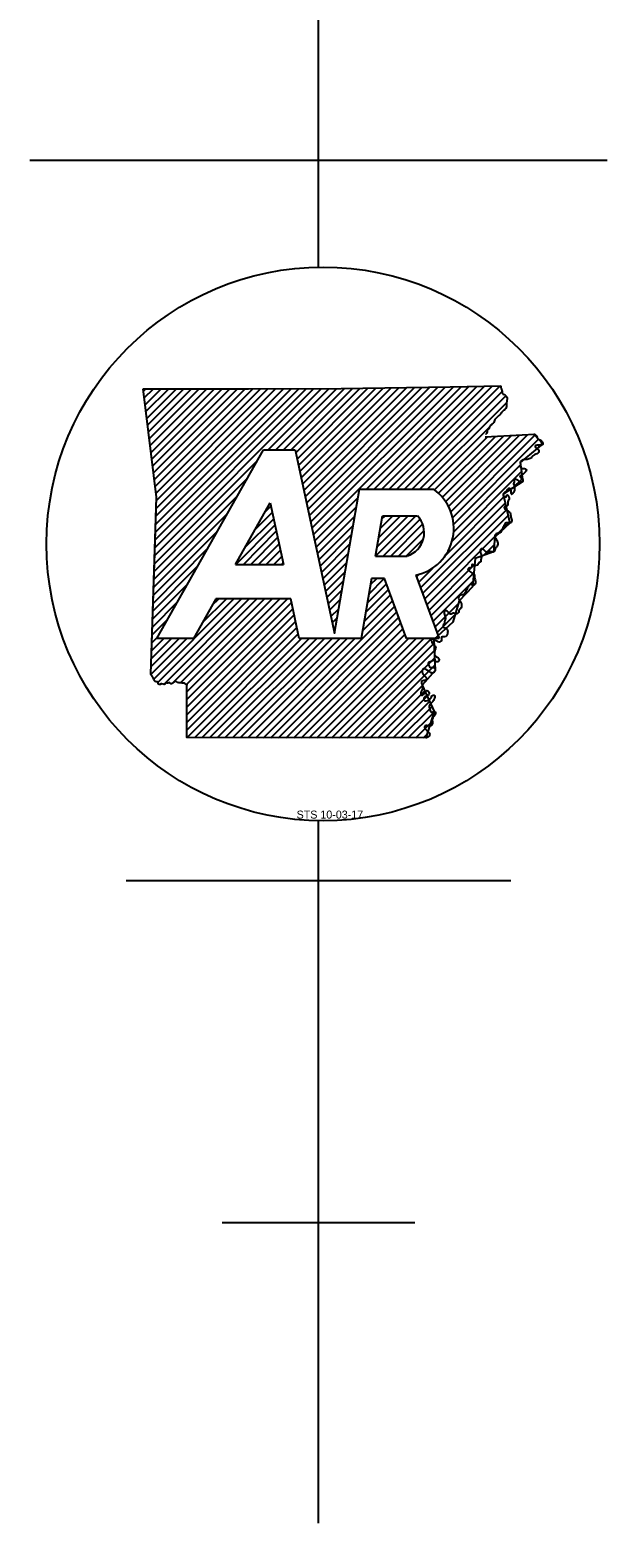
# Model space of a CAD drawing. Extents: x -43543 to 34500, y -13675 to 11152.
# Drawn here: x 5423 to 5949, y -831 to 528 of the extents above; entities that cross this region are included whole.
import ezdxf

# ---------------------------------------------------------------- set-up
doc = ezdxf.new("R2010")
doc.units = 0
doc.layers.add('R_Annotation', color=7, linetype='Continuous')

msp = doc.modelspace()

# ---------------------------------------------------------------- linework, layer by layer
at = {"layer": 'R_Annotation'}
for p, q in [((5685.7, 312.3), (5685.7, 1888.2)), ((5422.5, 409.7), (5948.8, 409.7)), ((5743.3, 110.2), (5837.1, 204)), ((5750.2, 110.2), (5844.2, 204.2)), ((5757.2, 110.2), (5851.4, 204.3)), ((5526, 199.4), (5528.2, 201.6)), ((5526.8, 193.2), (5535.2, 201.6)), ((5527.6, 187), (5542.1, 201.6)), ((5528.4, 180.8), (5549.1, 201.6)), ((5529.1, 174.6), (5556.1, 201.6)), ((5529.9, 168.5), (5563, 201.6)), ((5530.7, 162.3), (5570, 201.6)), ((5531.4, 156.1), (5576.9, 201.6)), ((5532.2, 149.9), (5583.9, 201.6)), ((5533, 143.7), (5590.9, 201.6)), ((5533.8, 137.5), (5597.8, 201.6)), ((5534.5, 131.3), (5604.8, 201.5)), ((5535.3, 125.1), (5611.8, 201.5)), ((5536.1, 118.9), (5618.7, 201.5)), ((5536.3, 49.5), (5688.5, 201.7)), ((5536.5, 56.7), (5681.5, 201.7)), ((5536.8, 63.9), (5674.5, 201.6)), ((5536.8, 112.7), (5625.7, 201.5)), ((5537, 71.1), (5667.6, 201.6)), ((5537.3, 78.3), (5660.6, 201.6)), ((5537.5, 85.5), (5653.6, 201.6)), ((5537.6, 106.5), (5632.7, 201.6)), ((5537.7, 92.7), (5646.6, 201.6)), ((5538, 99.9), (5639.6, 201.6)), ((5639.7, 145.9), (5695.5, 201.7)), ((5646.7, 145.9), (5702.5, 201.7)), ((5653.7, 145.9), (5709.5, 201.8)), ((5660.6, 145.9), (5716.6, 201.9)), ((5665, 143.3), (5723.6, 202)), ((5666.2, 137.6), (5730.7, 202.1)), ((5667.4, 131.8), (5737.8, 202.2)), ((5668.7, 126.1), (5744.9, 202.3)), ((5669.9, 120.4), (5752, 202.4)), ((5671.1, 114.6), (5759, 202.5)), ((5672.4, 108.9), (5766.1, 202.6)), ((5673.6, 103.2), (5773.2, 202.8)), ((5674.8, 97.4), (5780.3, 202.9)), ((5676, 91.7), (5787.3, 203)), ((5677.3, 85.9), (5794.4, 203.1)), ((5678.5, 80.2), (5801.5, 203.2)), ((5679.7, 74.5), (5808.6, 203.3)), ((5680.9, 68.7), (5815.7, 203.5)), ((5729.3, 110.2), (5822.8, 203.7)), ((5736.3, 110.2), (5830, 203.8)), ((5764.2, 110.2), (5852.9, 198.9)), ((5771.1, 110.2), (5856.3, 195.3)), ((5778.1, 110.2), (5857.2, 189.2)), ((5785.1, 110.2), (5841.3, 166.4)), ((5791.4, 109.5), (5839.9, 158)), ((5795.2, 106.4), (5847.3, 158.4)), ((5798.6, 102.8), (5854.6, 158.8)), ((5801.6, 98.8), (5861.9, 159.2)), ((5804.2, 94.5), (5869.3, 159.5)), ((5806.3, 89.6), (5876.6, 159.9)), ((5807.9, 84.2), (5883.2, 159.6)), ((5808.9, 78.2), (5886.5, 155.9)), ((5883.4, 145.8), (5889.7, 152.1)), ((5536.1, 42.3), (5630.1, 136.3)), ((5538.4, -25.7), (5635.5, 145.9)), ((5635.5, 145.9), (5664.4, 145.9)), ((5807.4, 62.9), (5870.7, 126.1)), ((5808.9, 71.3), (5869.9, 132.3)), ((5535.8, 35.1), (5621, 120.2)), ((5723, 110.2), (5790.5, 110.2)), ((5862.9, 111.3), (5871.5, 119.9)), ((5535.6, 27.9), (5611.9, 104.1)), ((5609.9, 41.7), (5641.6, 97.8)), ((5682.2, 63), (5721.7, 102.5)), ((5778.7, 20.2), (5855.9, 97.4)), ((5801.4, 49.9), (5854.6, 103.1)), ((5535.3, 20.7), (5602.8, 88.1)), ((5618.5, 57), (5644.8, 83.2)), ((5627.6, 73), (5643.5, 89)), ((5636.7, 89.1), (5642.3, 94.7)), ((5683.4, 57.3), (5720.2, 94.1)), ((5684.6, 51.5), (5718.8, 85.6)), ((5737.7, 49.3), (5774.4, 85.9)), ((5739.1, 57.7), (5767.4, 85.9)), ((5740.6, 66.1), (5760.4, 85.9)), ((5742.1, 74.5), (5753.5, 85.9)), ((5743.5, 83), (5746.5, 85.9)), ((5744.1, 85.9), (5775.7, 85.9)), ((5744.7, 49.3), (5778.2, 82.8)), ((5780.6, 15.1), (5857.2, 91.8)), ((5782.4, 10), (5858.5, 86.1)), ((5535.1, 13.5), (5593.7, 72)), ((5610.2, 41.7), (5646, 77.5)), ((5617.2, 41.7), (5647.2, 71.8)), ((5685.9, 45.8), (5717.3, 77.2)), ((5687.1, 40), (5715.8, 68.8)), ((5751.6, 49.3), (5780.6, 78.2)), ((5758.6, 49.3), (5781.9, 72.6)), ((5784.3, 4.9), (5859.8, 80.4)), ((5534.9, 6.2), (5584.6, 56)), ((5624.1, 41.7), (5648.4, 66)), ((5631.1, 41.7), (5649.7, 60.3)), ((5638.1, 41.7), (5650.9, 54.5)), ((5688.3, 34.3), (5714.3, 60.3)), ((5765.6, 49.3), (5781.3, 65)), ((5836, 49.7), (5845.8, 59.4)), ((5609.9, 41.7), (5653.6, 41.7)), ((5645, 41.7), (5652.1, 48.8)), ((5652, 41.7), (5653.4, 43.1)), ((5689.5, 28.6), (5712.9, 51.9)), ((5690.8, 22.8), (5711.4, 43.5)), ((5737.7, 49.3), (5766.6, 49.3)), ((5786.2, -0.2), (5828, 41.6)), ((5534.6, -1), (5575.5, 39.9)), ((5692, 17.1), (5709.9, 35)), ((5731.7, 15), (5745.6, 28.9)), ((5733.2, 23.4), (5738.7, 28.9)), ((5745.8, 28.9), (5734.1, 28.9)), ((5766, -25.7), (5745.8, 28.9)), ((5774.4, 31.8), (5795.6, -25.7)), ((5774.9, 30.4), (5777, 32.5)), ((5776.8, 25.3), (5790.1, 38.5)), ((5788.1, -5.2), (5827.2, 33.9)), ((5534.4, -8.2), (5566.4, 23.9)), ((5693.2, 11.4), (5708.5, 26.6)), ((5694.5, 5.6), (5707, 18.2)), ((5727.3, -10.3), (5751.4, 13.8)), ((5728.8, -1.9), (5749.5, 18.9)), ((5730.2, 6.6), (5747.6, 24)), ((5790, -10.3), (5826.4, 26.1)), ((5534.2, -15.4), (5557.3, 7.8)), ((5535.4, -62.9), (5608.6, 10.4)), ((5539.6, -65.7), (5615.6, 10.4)), ((5544.6, -67.6), (5622.6, 10.4)), ((5552.8, -66.3), (5629.5, 10.4)), ((5559.9, -66.2), (5636.5, 10.4)), ((5565.4, -67.7), (5643.5, 10.4)), ((5565.6, -81.4), (5657.4, 10.4)), ((5565.6, -74.5), (5650.4, 10.4)), ((5565.6, -88.4), (5661.1, 7.1)), ((5565.7, -95.3), (5662.3, 1.3)), ((5592.1, 10.4), (5571.7, -25.7)), ((5579.6, -11.7), (5601.7, 10.4)), ((5588.7, 4.4), (5594.7, 10.4)), ((5660.4, 10.4), (5592.1, 10.4)), ((5635.4, -116.2), (5755.2, 3.6)), ((5695.7, -0.1), (5705.5, 9.7)), ((5696.9, -5.9), (5704.1, 1.3)), ((5725.8, -18.7), (5753.3, 8.7)), ((5791.8, -15.4), (5813.2, 5.9)), ((5533.9, -22.6), (5548.2, -8.3)), ((5565.7, -102.3), (5663.5, -4.4)), ((5565.7, -109.2), (5664.7, -10.2)), ((5642.3, -116.2), (5757, -1.5)), ((5649.3, -116.2), (5758.9, -6.5)), ((5656.2, -116.2), (5760.8, -11.6)), ((5698.1, -11.6), (5702.6, -7.1)), ((5793.7, -20.5), (5810.2, -4)), ((5532.8, -58.5), (5565.7, -25.7)), ((5533, -51.4), (5558.7, -25.7)), ((5533.2, -44.2), (5551.7, -25.7)), ((5533.4, -37), (5544.8, -25.7)), ((5533.7, -29.8), (5539.1, -24.3)), ((5571.7, -25.7), (5538.4, -25.7)), ((5565.8, -116.1), (5666, -15.9)), ((5572.8, -116.1), (5667.2, -21.6)), ((5579.7, -116.1), (5670.1, -25.7)), ((5586.7, -116.1), (5677.1, -25.7)), ((5593.6, -116.1), (5684.1, -25.7)), ((5600.6, -116.1), (5691, -25.7)), ((5607.5, -116.1), (5698, -25.7)), ((5614.5, -116.1), (5705, -25.7)), ((5621.4, -116.1), (5711.9, -25.7)), ((5628.4, -116.2), (5718.9, -25.7)), ((5663.2, -116.2), (5762.7, -16.7)), ((5724.6, -25.7), (5668.1, -25.7)), ((5670.1, -116.2), (5764.6, -21.8)), ((5677.1, -116.2), (5767.7, -25.7)), ((5684, -116.3), (5774.6, -25.7)), ((5691, -116.3), (5781.6, -25.7)), ((5697.9, -116.3), (5788.6, -25.7)), ((5699.4, -17.3), (5701.1, -15.6)), ((5795.6, -25.7), (5766, -25.7)), ((5704.9, -116.3), (5790.9, -30.3)), ((5711.9, -116.3), (5791.2, -36.9)), ((5718.8, -116.3), (5791.5, -43.6)), ((5725.8, -116.3), (5791.8, -50.2)), ((5732.7, -116.3), (5780.4, -68.7)), ((5739.7, -116.3), (5782.5, -73.5)), ((5746.6, -116.4), (5784.7, -78.3)), ((5753.6, -116.4), (5786.8, -83.1)), ((5760.5, -116.4), (5789, -87.9)), ((5767.5, -116.4), (5790.8, -93.1)), ((5774.4, -116.4), (5787.6, -103.2)), ((5781.4, -116.4), (5784.5, -113.3)), ((5685.7, -831.4), (5685.7, -191.8)), ((5510.3, -246.1), (5861.1, -246.1)), ((5597.9, -557.7), (5773.4, -557.7))]:
    msp.add_line(p, q, dxfattribs=at)
for points in [[(5525.8, 201.5), (5621.9, 201.5), (5706.2, 201.7), (5805.7, 203.2), (5851.8, 204.3)], [(5525.8, 201.6), (5621.9, 201.5), (5706.2, 201.7), (5805.7, 203.3), (5851.8, 204.3)], [(5532.7, -58.4), (5538.1, 102.8), (5525.8, 201.6)], [(5536.4, 52.2), (5538.1, 102.8), (5525.8, 201.5)], [(5882, 160.2), (5890.3, 151.5), (5869.6, 134.4), (5871.8, 117.2), (5854, 105.5), (5860.1, 79.1), (5846.4, 66.6), (5845.2, 53), (5828.5, 47), (5825.9, 21.3), (5814, 8.5), (5808.2, -10.8), (5790.7, -26.8), (5792.1, -55), (5780.2, -68.2), (5791, -92.4), (5783.5, -116.4)], [(5837.5, 157.9), (5882.7, 160.2)], [(5837.6, 157.9), (5882.6, 160.2)], [(5664.4, 145.9), (5700.2, -21.1), (5723, 110.2)], [(5641.6, 97.8), (5653.6, 41.7)], [(5737.7, 49.3), (5744.1, 85.9)], [(5532.7, -58.4), (5536.4, 52.2)], [(5734.1, 28.9), (5724.6, -25.7)], [(5668.1, -25.7), (5660.4, 10.4)], [(5783.5, -116.4), (5565.7, -116.1), (5565.6, -68)], [(5783.5, -116.4), (5565.7, -116.1), (5565.6, -68)]]:
    msp.add_lwpolyline(points, dxfattribs=at)
msp.add_ellipse((5689.8, 60.3), major_axis=(252.1, 0), ratio=0.999976, dxfattribs=at)
for centre, major_axis, start_param, end_param in [((5765.4, 74.5), (-43.6, 0), 1.777838, 4.099264), ((5759.7, 70.5), (-22.3, 0), 1.887169, 3.90762)]:
    msp.add_ellipse(centre, major_axis=major_axis, ratio=0.999987, start_param=start_param, end_param=end_param, dxfattribs=at)
for points in [[(5851.8, 204.3), (5852.1, 201.7), (5852.9, 200.4), (5853, 197.8), (5854.1, 196.8), (5855.8, 195.7), (5857.3, 194), (5857.7, 192), (5857.2, 189.9), (5857.1, 187.5), (5856.9, 185.5), (5856.5, 183.7), (5855.1, 182.2), (5853.7, 181.2), (5852.5, 179.9), (5851.6, 178.6), (5850.1, 177.2), (5848.5, 175.7), (5847.2, 174.4), (5846, 172.7), (5845.4, 170.9), (5844, 169.6), (5842.9, 168.4), (5841.5, 166.8), (5840.8, 165.2), (5839.5, 163.3), (5839.1, 161.6), (5838.3, 160.1), (5838.2, 159.9)], [(5851.8, 204.3), (5852.1, 201.7), (5852.9, 200.3), (5853.1, 197.9), (5854.1, 196.8), (5855.8, 195.7), (5857.3, 194), (5857.7, 192), (5857.2, 189.9), (5857.1, 187.6), (5856.9, 185.6), (5856.5, 183.7), (5855.1, 182.2), (5853.7, 181.2), (5852.5, 179.9), (5851.6, 178.6), (5850, 177.2), (5848.5, 175.7), (5847.2, 174.4), (5846, 172.7), (5845.4, 170.9), (5844, 169.6), (5843, 168.4), (5841.5, 166.8), (5840.8, 165.2), (5839.4, 163.3), (5839.2, 161.5), (5838.3, 160.1), (5838.2, 159.9)], [(5882, 160.2), (5882.6, 160.2), (5884.7, 158.1), (5885.5, 156.3), (5886.9, 155.3), (5888.4, 154.8), (5889.5, 153.4), (5890.3, 151.9), (5889.9, 150.6), (5888.2, 150.5), (5886.3, 150.2), (5884.6, 150.3), (5883.1, 149), (5884.4, 147.5), (5886.2, 145.9), (5886.6, 144.4), (5885.7, 142.8), (5883.8, 142), (5881.9, 141.2), (5880.3, 139.9), (5879.5, 138.5), (5877.7, 137.9), (5875.8, 137.3), (5874.1, 137.2), (5872.2, 136.8), (5870.4, 135.9), (5869.6, 134.4), (5869.8, 132.2), (5869.8, 129.9), (5871.7, 129.1), (5873.4, 129), (5875.1, 128.2), (5874.9, 126.8), (5873.7, 125.2), (5872.2, 123.9), (5870.7, 123.2), (5869.3, 121.9), (5869.8, 120.7), (5871.1, 119.9), (5872, 118.5), (5871.8, 117.3), (5870.4, 116.4), (5868.9, 116.7), (5867.7, 118.2), (5866.4, 118.7), (5865.3, 119.2), (5864, 118.5), (5864, 116.7), (5863.5, 114.9), (5863.9, 113.5), (5864.4, 111.6), (5864.4, 110.2), (5863.9, 108.2), (5862.9, 106.1), (5861.8, 105.4), (5861.2, 107.7), (5861, 109.5), (5860.3, 110.6), (5859.3, 110.7), (5858.1, 109.8), (5856.8, 108.4), (5855, 106.9), (5854, 105.4), (5854.6, 103.6), (5855.8, 103.1), (5856.9, 103.5), (5857.4, 104.7), (5858.3, 104.8), (5859.3, 103)], [(5859.3, 103), (5859.6, 101.3), (5858.6, 99.5), (5858.2, 97.6), (5858.3, 95.7), (5856.5, 94.7), (5854.8, 93.5), (5855.8, 92.1), (5857.6, 90.8), (5859.3, 89.8), (5860.4, 88.8), (5860.8, 86.4), (5861.1, 84.8), (5861.7, 82.7), (5861.9, 81.2), (5860.8, 79.4), (5859.6, 79), (5858.3, 79.4), (5856.8, 79.6), (5855.5, 78.4), (5854.6, 76.7), (5853.7, 75.1), (5853, 73.6), (5852.4, 72.1), (5851.1, 70.3), (5849.5, 70), (5847.6, 69.5), (5846.4, 68.2), (5846.7, 66), (5847.7, 64.6), (5848.5, 62.7), (5849.1, 61.1), (5848.9, 59.1), (5848, 57.6), (5847, 56.7), (5846.4, 54.8), (5845.7, 53.4), (5845, 52.9), (5843.5, 53), (5842, 53.3), (5840.7, 53.2), (5839.5, 52.6), (5838.2, 53), (5836.9, 54.4), (5835.8, 55.5), (5834.6, 55.9), (5833.4, 55.2), (5833.2, 53.2), (5833.8, 51.2), (5834.3, 48.5), (5833.8, 46.9), (5833.6, 44.1)], [(5833.6, 44.1), (5831.5, 42.5), (5830.5, 40.9), (5825.3, 41.4), (5825.4, 39.5), (5823.5, 38.5), (5821.9, 37.3), (5822.8, 35.9), (5824.6, 34.6), (5826.4, 33.6), (5827.5, 32.6), (5827.8, 30.1), (5828.1, 28.6), (5828.7, 26.4), (5828.9, 25), (5827.9, 23.2), (5826.6, 22.8), (5825.3, 23.2), (5823.8, 23.3), (5822.5, 22.2), (5821.6, 20.5), (5820.8, 18.8), (5820.1, 17.4), (5819.4, 15.8), (5818.1, 14), (5816.5, 13.8), (5814.6, 13.3), (5813.5, 12), (5813.7, 9.8), (5814.7, 8.3), (5815.6, 6.5), (5816.1, 4.9), (5815.9, 2.9), (5815.1, 1.3), (5814, 0.4), (5813.5, -1.4), (5812.7, -2.9), (5812, -3.3), (5810.6, -3.2), (5809.1, -2.9), (5807.7, -3), (5806.5, -3.7), (5805.2, -3.3), (5803.9, -1.9), (5802.8, -0.8), (5801.7, -0.4), (5800.4, -1), (5800.2, -3), (5800.8, -5), (5801.3, -7.7), (5800.8, -9.4), (5800.6, -12.2)], [(5800.6, -12.2), (5800.5, -12.2), (5799.4, -13.6), (5800, -15.7), (5802.3, -16.5), (5803.4, -18.5), (5803.4, -20.3), (5802.7, -22.7), (5801.6, -23.9), (5799.5, -24.4), (5797.9, -24.7), (5797.7, -27.4), (5796.9, -28.7), (5795.7, -29.2), (5793.9, -28.3), (5792.8, -27.8), (5791.5, -27.2), (5789.9, -26.3), (5788.6, -26.5), (5789, -29), (5789.1, -29.2), (5790.5, -31.1), (5791.9, -32.7), (5792.6, -34.5)], [(5800.6, -12.2), (5800.5, -12.2), (5799.4, -13.6), (5800, -15.7), (5802.3, -16.5), (5803.4, -18.5), (5803.4, -20.3), (5802.7, -22.7), (5801.6, -23.9), (5799.5, -24.4), (5797.9, -24.7), (5797.7, -27.4), (5796.9, -28.7), (5795.7, -29.2), (5793.9, -28.3), (5792.8, -27.8), (5791.5, -27.2), (5789.9, -26.3), (5788.6, -26.5), (5789, -29), (5789.1, -29.2), (5790.5, -31.1), (5791.9, -32.7), (5792.6, -34.5)], [(5792.6, -34.5), (5792, -35.9), (5791.3, -38.3), (5791.5, -40.3), (5792.5, -42), (5793.9, -42.9), (5795.4, -44.3), (5795.3, -46.4), (5794.4, -47.2), (5792.3, -46.7), (5790.7, -45.9), (5789.3, -46.3), (5787.5, -47.2), (5786.1, -47.5), (5786.2, -50.3), (5788, -52.3), (5789.6, -52.3), (5791.5, -52.5), (5792.1, -54.7), (5791.1, -56.5), (5789.3, -57.3), (5787, -56.2), (5785.4, -55.1), (5783.8, -54.1), (5781.8, -53.5), (5780.7, -53.8), (5780.1, -56.2), (5781.1, -58.5), (5782.6, -60.1), (5784, -62.1), (5783.8, -63.6), (5782.8, -64), (5780.8, -64.4), (5779.7, -65), (5779.4, -65.5), (5780, -67.5), (5780.5, -69.7), (5780.5, -71.4), (5779.9, -72.9), (5778.9, -75.2), (5779, -76.8), (5779.7, -77.5), (5780.6, -77.3), (5781.8, -76.5), (5782.6, -75.5), (5783.2, -74.3), (5784.5, -73.3), (5786, -74.2), (5786.4, -76.1), (5785.5, -77.6), (5784.2, -78.4), (5782.7, -79), (5781.6, -80.3), (5781.8, -81.8), (5782.8, -82.7), (5785, -82.2), (5786.4, -81.6), (5787.3, -80.8), (5788.3, -79.8), (5788.8, -78.7), (5789.6, -77.6), (5791, -77.4), (5791.6, -78.2), (5791.3, -80.3), (5790.5, -82.2), (5789.4, -83.8), (5788.2, -84.9), (5786.6, -87.3), (5786.9, -89.6), (5787.5, -91.5), (5788.3, -92.9), (5789.8, -92.6), (5791.3, -92.4), (5792.3, -93.2), (5792.2, -94.8), (5791, -96.5), (5789.9, -98), (5789.3, -100.1), (5789.5, -101.6), (5789.5, -103), (5789.1, -104.5), (5788.2, -105.3), (5786, -105.3), (5783.7, -105), (5782.5, -105.7), (5782.7, -107.7), (5784, -109.2), (5785, -110), (5786.4, -111.7), (5787, -113), (5786.8, -114.2), (5785.9, -115.3), (5783.5, -116.4)], [(5792.6, -34.5), (5792, -35.9), (5791.3, -38.3), (5791.5, -40.3), (5792.5, -42), (5793.9, -42.9), (5795.4, -44.3), (5795.3, -46.4), (5794.4, -47.2), (5792.3, -46.7), (5790.7, -45.9), (5789.3, -46.3), (5787.5, -47.2), (5786.1, -47.5), (5786.2, -50.3), (5788, -52.3), (5789.6, -52.3), (5791.5, -52.5), (5792.1, -54.7), (5791.1, -56.5), (5789.3, -57.3), (5787, -56.2), (5785.4, -55.1), (5783.8, -54.1), (5781.8, -53.5), (5780.7, -53.8), (5780.1, -56.2), (5781.1, -58.5), (5782.6, -60.1), (5784, -62.1), (5783.8, -63.6), (5782.8, -64), (5780.8, -64.4), (5779.7, -65), (5779.4, -65.5), (5780, -67.5), (5780.5, -69.7), (5780.5, -71.4), (5779.9, -72.9), (5778.9, -75.2), (5779, -76.8), (5779.7, -77.5), (5780.6, -77.3), (5781.8, -76.5), (5782.6, -75.5), (5783.2, -74.3), (5784.5, -73.3), (5786, -74.2), (5786.4, -76.1), (5785.5, -77.6), (5784.2, -78.4), (5782.7, -79), (5781.6, -80.3), (5781.8, -81.8), (5782.8, -82.7), (5785, -82.2), (5786.4, -81.6), (5787.3, -80.8), (5788.3, -79.8), (5788.8, -78.7), (5789.6, -77.6), (5791, -77.4), (5791.6, -78.2), (5791.3, -80.3), (5790.5, -82.2), (5789.4, -83.8), (5788.2, -84.9), (5786.6, -87.3), (5786.9, -89.6), (5787.5, -91.5), (5788.3, -92.9), (5789.8, -92.6), (5791.3, -92.4), (5792.3, -93.2), (5792.2, -94.8), (5791, -96.5), (5789.9, -98), (5789.3, -100.1), (5789.5, -101.6), (5789.5, -103), (5789.1, -104.5), (5788.2, -105.3), (5786, -105.3), (5783.7, -105), (5782.5, -105.7), (5782.7, -107.7), (5784, -109.2), (5785, -110), (5786.4, -111.7), (5787, -113), (5786.8, -114.2), (5785.9, -115.3), (5783.5, -116.4)], [(5565.6, -68), (5565.8, -68.1), (5564.7, -67.3), (5563.2, -66.6), (5561.4, -66.4), (5559.2, -66.2), (5557.4, -66), (5555.5, -64.7), (5553.5, -66), (5551.2, -67), (5549.9, -65.9), (5548.2, -66.6), (5547, -66.2), (5544.9, -67.7), (5542.9, -67.1), (5541.5, -67.5), (5539.8, -67.5), (5539.4, -65.5), (5537.6, -65.2), (5536.2, -64.3), (5535.2, -62.3), (5534.4, -60.6), (5532.7, -58.4)], [(5565.6, -68), (5565.8, -68.1), (5564.7, -67.3), (5563.2, -66.6), (5561.4, -66.4), (5559.2, -66.1), (5557.4, -66), (5555.5, -64.7), (5553.5, -66), (5551.2, -67), (5549.9, -65.9), (5548.2, -66.6), (5547, -66.3), (5544.9, -67.7), (5542.9, -67.1), (5541.5, -67.6), (5539.7, -67.5), (5539.4, -65.5), (5537.7, -65.2), (5536.2, -64.4), (5535.2, -62.3), (5534.4, -60.7), (5532.7, -58.4)]]:
    msp.add_spline(points, degree=3, dxfattribs=at)

# ---------------------------------------------------------------- texts
msp.add_text('STS 10-03-17', height=7.288, dxfattribs=at).set_placement((5665.7, -189.8))

doc.saveas('drawing.dxf')
